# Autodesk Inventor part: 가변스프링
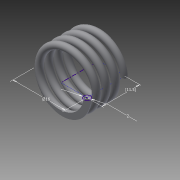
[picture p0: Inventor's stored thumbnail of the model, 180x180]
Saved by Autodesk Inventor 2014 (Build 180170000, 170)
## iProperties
Created: 2015-04
Part Number: 가변스프링
Material: Generic
Document SubType Name: Modeling
Designer: 시험용
Density: 1 g/cm^3
Appearance: Default
Author: 시험용
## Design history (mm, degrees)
sketch "스케치1"
  geometry: L1 (0, 0)-(8, 0); L2 (8, 0)-(8, 11.5); L3 (8, 11.5)-(0, 11.5); L4 (0, 11.5)-(0, 0); C1 r 1 at (8, 0)
  constraints: 8 end point, 2 parallel, 1 centre point, 1 coincident, 1 horizontal, 1 perpendicular
  dimensions: "d0" = 11.50049 distance of L1.end L2.end (derived); "d1" = 16 diameter of L2 L4; "d2" = 2 diameter of C1
feature "코일1" sketch "스케치1" pitch "d3" = 10; turns "d5" = 4; dims "d4" = 11.50049 (= d0), "d6" = 0, angle "d7" = 90 deg, angle "d8" = 90 deg, "d9" = 0, "d10" = 0
sketch "스케치2"
  geometry: L1 (-9, 0)-(-7, 0) reference; 1 further point
  constraints: 1 horizontal alignment
extrude "돌출1" cut sketch "스케치2" stored distance "d11" = 10; taper "d12" = 0 deg
node "작업 평면2"
sketch "스케치3"
  geometry: L1 (1, 0)-(-1, 0) reference; 1 further point
  constraints: 1 horizontal alignment
extrude "돌출2" cut sketch "스케치3" stored distance "d14" = 10; taper "d15" = 0 deg
node "솔리드1"
node "절단 모서리 투영1"
node "절단 모서리 투영2"
other parameters: "d13" = 0
